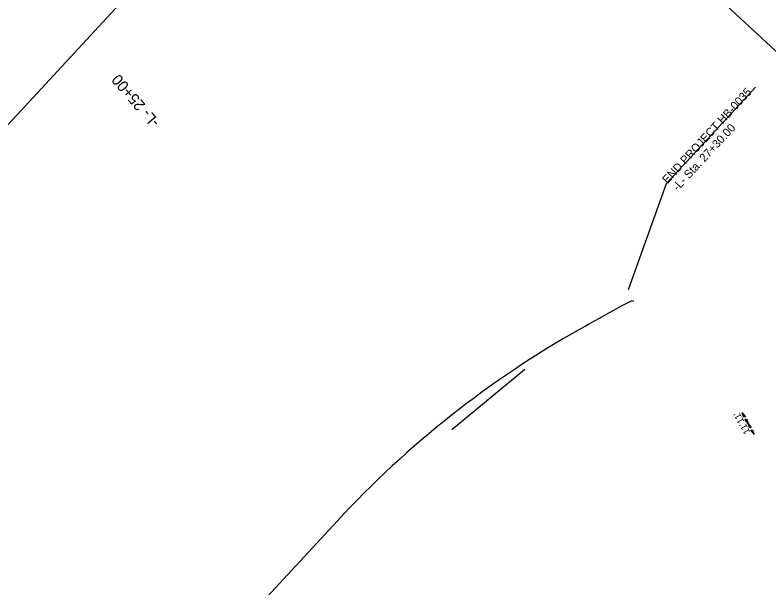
# Model space of a CAD drawing. Extents: x 1768064 to 1770025, y 999327 to 1001342.
# Drawn here: x 1768809 to 1769490, y 1000306 to 1000824 of the extents above; entities that cross this region are included whole.
import ezdxf

# ---------------------------------------------------------------- set-up
doc = ezdxf.new("R2010")
doc.units = 0
for name, color, linetype in [('E_NCDOT_Terrain_Model_Boundary', 7, 'Continuous'), ('E_NCDOT_Terrain_Model_Breakline', 7, 'Continuous'), ('E_NCDOT_Terrain_Model_Contour_Minor', 7, 'Continuous'), ('E_NCDOT_Terrain_Model_Hole', 7, 'Continuous'), ('E_NCDOT_Terrain_Model_Triangles', 7, 'Continuous'), ('P_NCDOT_Horizontal_Alignment', 7, 'Continuous'), ('P_NCDOT_Horizontal_Alignment_Tick_Small', 7, 'Continuous')]:
    doc.layers.add(name, color=color, linetype=linetype)

msp = doc.modelspace()

# ---------------------------------------------------------------- linework, layer by layer
at = {"layer": 'E_NCDOT_Terrain_Model_Boundary'}
msp.add_line((1768828.51, 1000072.87), (1769100.08, 1000366.66), dxfattribs=at)
msp.add_lwpolyline([(1769319.87, 1000540.46), (1769324.18, 1000542.88), (1769327.6, 1000544.87), (1769328.45, 1000545.36), (1769332.74, 1000547.82), (1769337.04, 1000550.25), (1769338.07, 1000550.83), (1769341.36, 1000552.66), (1769345.69, 1000555.05), (1769350.03, 1000557.41), (1769354.39, 1000559.75), (1769358.76, 1000562.06), (1769363.14, 1000564.35), (1769366.8, 1000566.24), (1769367.74, 1000565.6), (1769367.97, 1000565.72)], dxfattribs=at)
msp.add_arc((1769763.92, 999753.04), 904, 119.4197, 137.25123, dxfattribs=at)
at = {"layer": 'E_NCDOT_Terrain_Model_Breakline'}
for q in [(1769478.13, 1000759.04), (1769363.16, 1000575.61)]:
    msp.add_line((1769397.4, 1000671.69), q, dxfattribs=at)
at = {"layer": 'E_NCDOT_Terrain_Model_Contour_Minor'}
for points in [[(1769467.62, 1000460.17), (1769466.11, 1000464.48), (1769469.01, 1000460.91), (1769468.03, 1000461.02)], [(1769469.95, 1000459.17), (1769471.46, 1000454.87), (1769468.56, 1000458.43), (1769469.54, 1000458.32)], [(1769472.98, 1000450.56), (1769471.46, 1000454.87), (1769474.37, 1000451.3), (1769473.39, 1000451.42)], [(1769475.3, 1000449.56), (1769476.82, 1000445.26), (1769473.92, 1000448.82), (1769474.9, 1000448.71)]]:
    msp.add_lwpolyline(points, close=True, dxfattribs=at)
at = {"layer": 'P_NCDOT_Horizontal_Alignment'}
msp.add_line((1769203.69, 1000449.52), (1769269.74, 1000504.03), dxfattribs=at)
at = {"layer": 'P_NCDOT_Horizontal_Alignment_Tick_Small'}
msp.add_lwpolyline([(1768865.94, 999468.18), (1769816.23, 1000496.25), (1769155.33, 1001107.16), (1768205.03, 1000079.09)], close=True, dxfattribs=at)

# ---------------------------------------------------------------- texts
at = {"layer": 'E_NCDOT_Terrain_Model_Breakline'}
for s, p in [('END PROJECT HB-0035', (1769398.58, 1000671.13)), ('-L- Sta. 27+30.00', (1769407.91, 1000664.64))]:
    msp.add_text(s, height=7.5, rotation=47.25123, dxfattribs=at).set_placement(p)
at = {"layer": 'E_NCDOT_Terrain_Model_Hole'}
msp.add_text('-L- 25+00', height=10, rotation=130.37791, dxfattribs=at).set_placement((1768940.23, 1000727.8))
at = {"layer": 'E_NCDOT_Terrain_Model_Triangles'}
for p in [(1769468.16, 1000456.79), (1769473.52, 1000447.18)]:
    msp.add_text("11'", height=6, rotation=119.12308, dxfattribs=at).set_placement(p)

doc.saveas('drawing.dxf')
